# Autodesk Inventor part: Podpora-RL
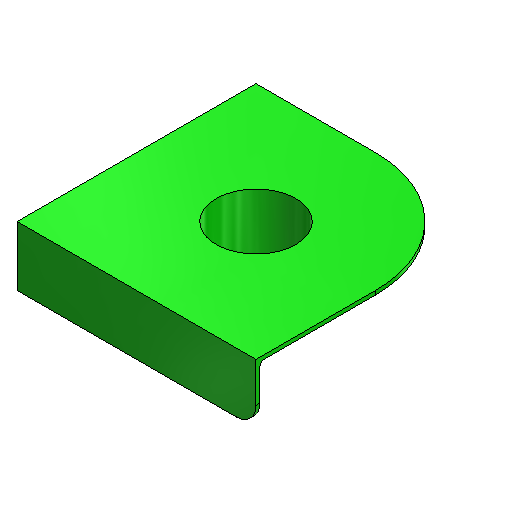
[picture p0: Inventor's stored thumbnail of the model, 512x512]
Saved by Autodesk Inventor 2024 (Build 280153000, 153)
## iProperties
Company: ATC
Shininess: 20.0
Angle Display Precision: 2
Document Length Units: 11269
Document Angle Units: 11279
Document Time Units: 11290
Document Mass Units: 11283
Document Length Units Precision: 3
Document Angle Units Precision: 2
Created: 2023-03
Part Number: Podpora-RL
Material: Stal węglowa
Document SubType Name: Modelowanie
Designer: Andrzej Jaskulski
Density: 7.87 g/cm^3
Stock Number: Podpora-RL
Appearance: LED — zielone włączone
Checked By: A.J.
Engr Approved By: Andrzej Jaskulski
Mfg Approved By: Andrzej Jaskulski
Authority: A.J.
Density: 0.0
Volumn: 0.0
Area: 0.0
PropertySet Name: Model Information
Control State: 0
Master: False
Checked Out: False
Title: A.J.: Kurs R2024-MEP
Author: Andrzej Jaskulski
Revision Number: 1/24
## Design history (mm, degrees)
feature "Bryła1::Podpora-RP" dims "d13" = 10
node "Bryła1"
node "Początek"
  node "Płaszczyzna YZ"
  node "Płaszczyzna XZ"
  node "Płaszczyzna XY"
  node "Oś X"
  node "Oś Y"
  node "Oś Z"
node "Podpora-RP" dims "d13" = 10
node "Korpusy bryłowe"
node "Korpusy powierzchniowe"
node "Punkt środkowy"
tag "Bryła wyprowadzona3"
